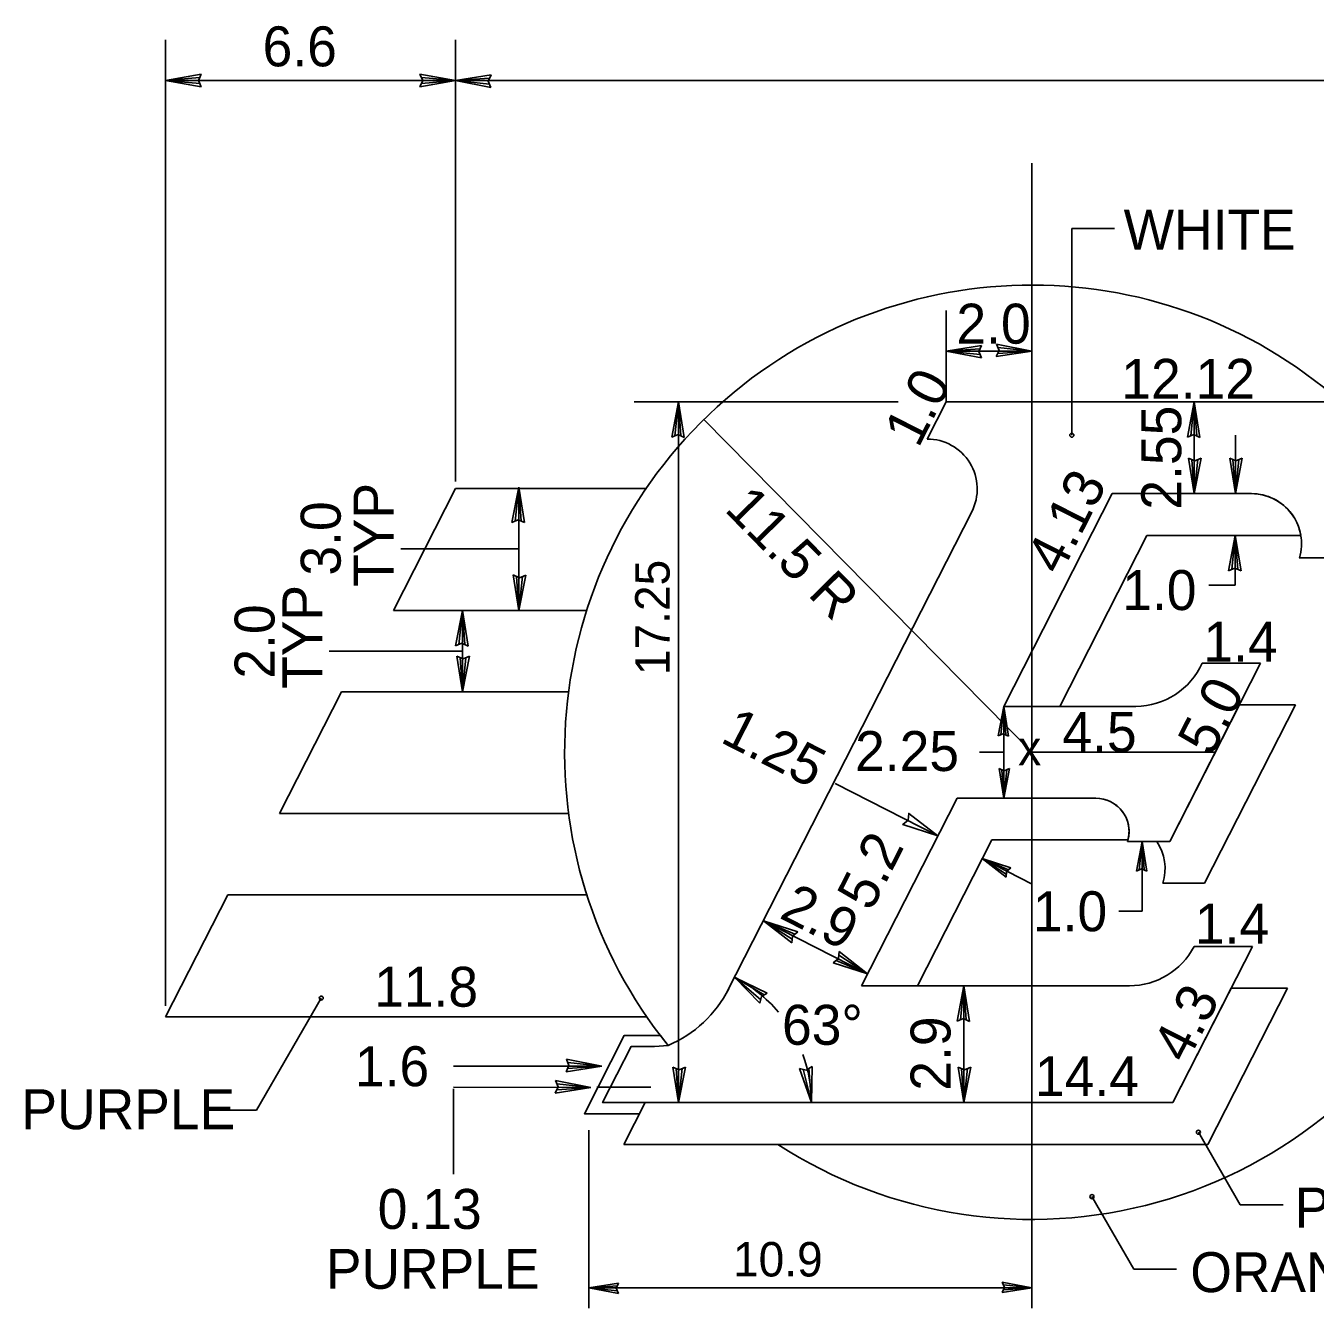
# Model space of a CAD drawing. Extents: x 10268197 to 10269179, y 2141503 to 2142677.
# Drawn here: x 10268594.16 to 10268616.76, y 2141973.76 to 2141996.23 of the extents above; entities that cross this region are included whole.
import ezdxf

# ---------------------------------------------------------------- set-up
doc = ezdxf.new("R2010")
doc.units = 0
for name, color, linetype in [('1', 7, 'Continuous'), ('20', 7, 'Continuous'), ('21', 7, 'Continuous'), ('52', 7, 'Continuous'), ('NonPlottingEle_dp', 7, 'Continuous'), ('North Arrow', 7, 'Continuous')]:
    doc.layers.add(name, color=color, linetype=linetype)

msp = doc.modelspace()

# ---------------------------------------------------------------- linework, layer by layer
at = {"layer": '1'}
for p, q in [((10268611.789, 2141983.501), (10268611.789, 2141993.824)), ((10268610.286, 2141989.641), (10268609.955, 2141988.99)), ((10268618.911, 2141989.641), (10268610.286, 2141989.641)), ((10268611.789, 2141983.501), (10268606.044, 2141989.334)), ((10268601.689, 2141988.121), (10268600.601, 2141985.986)), ((10268601.689, 2141988.121), (10268605.031, 2141988.121)), ((10268613.197, 2141988.033), (10268611.298, 2141984.305)), ((10268613.197, 2141988.033), (10268611.298, 2141984.305)), ((10268613.197, 2141988.033), (10268615.637, 2141988.033)), ((10268615.637, 2141988.033), (10268613.197, 2141988.033)), ((10268606.459, 2141979.318), (10268610.738, 2141987.715)), ((10268613.808, 2141987.302), (10268612.281, 2141984.305)), ((10268612.281, 2141984.305), (10268613.808, 2141987.302)), ((10268613.808, 2141987.302), (10268616.502, 2141987.302)), ((10268613.808, 2141987.302), (10268616.502, 2141987.302)), ((10268602.8, 2141987.067), (10268600.729, 2141987.067)), ((10268616.478, 2141986.906), (10268617.518, 2141986.906)), ((10268600.601, 2141985.986), (10268603.988, 2141985.986)), ((10268601.811, 2141985.274), (10268599.474, 2141985.274)), ((10268614.208, 2141981.938), (10268615.8, 2141985.064)), ((10268614.775, 2141985.065), (10268615.8, 2141985.064)), ((10268599.694, 2141984.562), (10268598.604, 2141982.426)), ((10268599.694, 2141984.562), (10268603.671, 2141984.562)), ((10268611.298, 2141984.305), (10268613.61, 2141984.305)), ((10268611.298, 2141984.305), (10268612.281, 2141984.305)), ((10268615.428, 2141984.333), (10268614.208, 2141981.938)), ((10268614.819, 2141981.207), (10268616.413, 2141984.333)), ((10268614.819, 2141981.207), (10268616.413, 2141984.333)), ((10268615.428, 2141984.333), (10268616.413, 2141984.333)), ((10268616.413, 2141984.333), (10268615.428, 2141984.333)), ((10268611.298, 2141983.501), (10268610.873, 2141983.501)), ((10268611.789, 2141973.759), (10268611.789, 2141983.501)), ((10268615.004, 2141983.501), (10268611.789, 2141983.501)), ((10268610.479, 2141982.697), (10268608.803, 2141979.408)), ((10268610.479, 2141982.697), (10268608.803, 2141979.408)), ((10268610.479, 2141982.697), (10268612.909, 2141982.697)), ((10268612.909, 2141982.697), (10268610.479, 2141982.697)), ((10268598.604, 2141982.426), (10268603.673, 2141982.427)), ((10268611.09, 2141981.966), (10268609.787, 2141979.407)), ((10268609.787, 2141979.407), (10268611.09, 2141981.966)), ((10268611.09, 2141981.966), (10268613.476, 2141981.966)), ((10268611.09, 2141981.966), (10268613.476, 2141981.966)), ((10268613.467, 2141981.938), (10268614.208, 2141981.938)), ((10268614.208, 2141981.938), (10268613.981, 2141981.938)), ((10268614.819, 2141981.207), (10268614.088, 2141981.207)), ((10268614.088, 2141981.207), (10268614.819, 2141981.207)), ((10268597.698, 2141981.003), (10268596.609, 2141978.867)), ((10268597.698, 2141981.003), (10268603.993, 2141981.003)), ((10268615.657, 2141980.096), (10268614.263, 2141977.361)), ((10268614.633, 2141980.096), (10268615.657, 2141980.096)), ((10268608.803, 2141979.408), (10268613.499, 2141979.408)), ((10268608.803, 2141979.408), (10268609.787, 2141979.407)), ((10268615.285, 2141979.365), (10268614.263, 2141977.361)), ((10268616.269, 2141979.365), (10268614.875, 2141976.63)), ((10268614.875, 2141976.63), (10268616.269, 2141979.365)), ((10268615.285, 2141979.365), (10268616.269, 2141979.365)), ((10268616.269, 2141979.365), (10268615.285, 2141979.365)), ((10268596.609, 2141978.867), (10268605.04, 2141978.867)), ((10268614.263, 2141977.361), (10268604.267, 2141977.361)), ((10268604.641, 2141976.63), (10268605.013, 2141977.361)), ((10268605.013, 2141977.361), (10268604.641, 2141976.63)), ((10268614.263, 2141977.361), (10268605.013, 2141977.361)), ((10268604.914, 2141977.166), (10268603.949, 2141977.166)), ((10268604.029, 2141973.759), (10268604.029, 2141976.879)), ((10268614.875, 2141976.63), (10268604.641, 2141976.63)), ((10268604.641, 2141976.63), (10268614.875, 2141976.63))]:
    msp.add_line(p, q, dxfattribs=at)
for centre, radius, start, end in [((10268611.789, 2141983.501), 8.187, 48.5904, 218.8792), ((10268609.956, 2141988.113), 0.877, 333.0033, 90.1042), ((10268615.638, 2141987.156), 0.877, 343.4611, 90), ((10268615.638, 2141987.156), 0.877, 9.5941, 90), ((10268613.611, 2141985.577), 1.272, 270, 336.2493), ((10268612.909, 2141982.112), 0.585, 342.6625, 90), ((10268612.909, 2141982.112), 0.585, 345.5225, 90), ((10268613.248, 2141981.457), 0.877, 343.4611, 33.2756), ((10268613.248, 2141981.457), 0.877, 343.4611, 33.2756), ((10268613.498, 2141980.687), 1.279, 270, 332.5096), ((10268611.789, 2141983.501), 8.187, 237.0648, 334.1734), ((10268604.576, 2141980.326), 2.136, 293.1567, 333.0112)]:
    msp.add_arc(centre, radius, start, end, dxfattribs=at)
at = {"layer": '20'}
for p, q in [((10268596.609, 2141979.056), (10268596.609, 2141995.984)), ((10268601.689, 2141989.283), (10268601.689, 2141995.984)), ((10268601.689, 2141995.272), (10268596.609, 2141995.272)), ((10268648.726, 2141995.272), (10268601.689, 2141995.272)), ((10268612.491, 2141992.679), (10268613.241, 2141992.68)), ((10268612.491, 2141989.057), (10268612.491, 2141992.679)), ((10268610.286, 2141989.641), (10268610.286, 2141991.243)), ((10268611.789, 2141990.532), (10268610.286, 2141990.532)), ((10268609.449, 2141989.641), (10268604.818, 2141989.641)), ((10268605.599, 2141977.361), (10268605.598, 2141989.641)), ((10268614.637, 2141989.641), (10268614.637, 2141988.033)), ((10268601.689, 2141988.246), (10268601.689, 2141989.283)), ((10268615.357, 2141989.059), (10268615.357, 2141988.033)), ((10268602.799, 2141988.149), (10268602.8, 2141985.986)), ((10268615.356, 2141987.302), (10268615.356, 2141986.426)), ((10268614.893, 2141986.426), (10268615.356, 2141986.426)), ((10268601.811, 2141985.986), (10268601.811, 2141984.562)), ((10268611.298, 2141984.305), (10268611.298, 2141982.697)), ((10268610.141, 2141982.034), (10268608.341, 2141982.952)), ((10268613.722, 2141981.938), (10268613.722, 2141980.714)), ((10268610.922, 2141981.637), (10268611.797, 2141981.191)), ((10268613.722, 2141980.714), (10268613.314, 2141980.715)), ((10268607.086, 2141980.549), (10268608.911, 2141979.619)), ((10268610.6, 2141979.407), (10268610.6, 2141977.361)), ((10268599.336, 2141979.193), (10268598.203, 2141977.231)), ((10268604.252, 2141978.002), (10268601.655, 2141978.002)), ((10268604.063, 2141977.629), (10268601.655, 2141977.63)), ((10268601.655, 2141976.11), (10268601.655, 2141977.606)), ((10268605.114, 2141977.63), (10268604.166, 2141977.63)), ((10268598.203, 2141977.231), (10268597.454, 2141977.231)), ((10268614.71, 2141976.843), (10268615.444, 2141975.571)), ((10268612.843, 2141975.714), (10268613.577, 2141974.443)), ((10268615.444, 2141975.571), (10268616.194, 2141975.571)), ((10268613.577, 2141974.443), (10268614.327, 2141974.442)), ((10268611.789, 2141974.117), (10268604.029, 2141974.117))]:
    msp.add_line(p, q, dxfattribs=at)
for centre in [(10268612.491, 2141989.057), (10268599.336, 2141979.193), (10268614.71, 2141976.843), (10268612.843, 2141975.714)]:
    msp.add_circle(centre, 0.0356, dxfattribs=at)
for start, end in [(40.0298, 62.999), (0, 19.9667)]:
    msp.add_arc((10268605.462, 2141977.361), 2.465, start, end, dxfattribs=at)
at = {"layer": '21'}
for p, q in [((10268596.609, 2141995.272), (10268597.231, 2141995.382)), ((10268597.183, 2141995.272), (10268597.231, 2141995.382)), ((10268601.689, 2141995.272), (10268601.067, 2141995.382)), ((10268601.067, 2141995.382), (10268601.115, 2141995.272)), ((10268601.689, 2141995.272), (10268602.313, 2141995.371)), ((10268602.263, 2141995.262), (10268602.313, 2141995.371)), ((10268596.609, 2141995.272), (10268597.205, 2141995.324)), ((10268596.609, 2141995.272), (10268597.23, 2141995.162)), ((10268596.609, 2141995.272), (10268597.206, 2141995.22)), ((10268597.23, 2141995.162), (10268597.183, 2141995.272)), ((10268601.689, 2141995.272), (10268601.067, 2141995.162)), ((10268601.115, 2141995.272), (10268601.067, 2141995.162)), ((10268601.689, 2141995.272), (10268601.092, 2141995.324)), ((10268601.689, 2141995.272), (10268601.092, 2141995.22)), ((10268601.689, 2141995.272), (10268602.286, 2141995.314)), ((10268601.689, 2141995.272), (10268602.309, 2141995.152)), ((10268601.689, 2141995.272), (10268602.285, 2141995.21)), ((10268602.309, 2141995.152), (10268602.263, 2141995.262)), ((10268610.286, 2141990.532), (10268610.91, 2141990.63)), ((10268610.86, 2141990.522), (10268610.91, 2141990.63)), ((10268611.789, 2141990.532), (10268611.169, 2141990.652)), ((10268611.169, 2141990.652), (10268611.215, 2141990.541)), ((10268610.286, 2141990.532), (10268610.884, 2141990.573)), ((10268610.286, 2141990.532), (10268610.906, 2141990.411)), ((10268610.286, 2141990.532), (10268610.882, 2141990.469)), ((10268610.906, 2141990.411), (10268610.86, 2141990.522)), ((10268611.215, 2141990.541), (10268611.165, 2141990.433)), ((10268611.789, 2141990.532), (10268611.165, 2141990.433)), ((10268611.789, 2141990.532), (10268611.192, 2141990.49)), ((10268611.789, 2141990.532), (10268611.193, 2141990.594)), ((10268605.598, 2141989.641), (10268605.478, 2141989.021)), ((10268605.598, 2141989.641), (10268605.536, 2141989.045)), ((10268605.598, 2141989.641), (10268605.698, 2141989.017)), ((10268605.598, 2141989.641), (10268605.64, 2141989.044)), ((10268614.637, 2141989.641), (10268614.517, 2141989.021)), ((10268614.637, 2141989.641), (10268614.575, 2141989.045)), ((10268614.637, 2141989.641), (10268614.736, 2141989.017)), ((10268614.637, 2141989.641), (10268614.679, 2141989.044)), ((10268605.478, 2141989.021), (10268605.589, 2141989.067)), ((10268605.589, 2141989.067), (10268605.698, 2141989.017)), ((10268614.517, 2141989.021), (10268614.628, 2141989.067)), ((10268614.628, 2141989.067), (10268614.736, 2141989.017)), ((10268614.637, 2141988.033), (10268614.538, 2141988.657)), ((10268614.647, 2141988.608), (10268614.538, 2141988.657)), ((10268614.637, 2141988.033), (10268614.596, 2141988.63)), ((10268614.637, 2141988.033), (10268614.758, 2141988.653)), ((10268614.637, 2141988.033), (10268614.7, 2141988.629)), ((10268614.758, 2141988.653), (10268614.647, 2141988.608)), ((10268615.357, 2141988.033), (10268615.258, 2141988.657)), ((10268615.366, 2141988.607), (10268615.258, 2141988.657)), ((10268615.357, 2141988.033), (10268615.315, 2141988.63)), ((10268615.357, 2141988.033), (10268615.477, 2141988.653)), ((10268615.357, 2141988.033), (10268615.419, 2141988.629)), ((10268615.477, 2141988.653), (10268615.366, 2141988.607)), ((10268602.799, 2141988.149), (10268602.679, 2141987.529)), ((10268602.799, 2141988.149), (10268602.737, 2141987.553)), ((10268602.799, 2141988.149), (10268602.898, 2141987.525)), ((10268602.799, 2141988.149), (10268602.841, 2141987.551)), ((10268602.679, 2141987.529), (10268602.79, 2141987.574)), ((10268602.79, 2141987.574), (10268602.898, 2141987.525)), ((10268615.356, 2141987.302), (10268615.236, 2141986.682)), ((10268615.356, 2141987.302), (10268615.294, 2141986.706)), ((10268615.356, 2141987.302), (10268615.456, 2141986.678)), ((10268615.356, 2141987.302), (10268615.398, 2141986.705)), ((10268602.8, 2141985.986), (10268602.701, 2141986.61)), ((10268602.81, 2141986.56), (10268602.701, 2141986.61)), ((10268602.8, 2141985.986), (10268602.758, 2141986.583)), ((10268602.8, 2141985.986), (10268602.92, 2141986.606)), ((10268602.8, 2141985.986), (10268602.862, 2141986.582)), ((10268602.92, 2141986.606), (10268602.81, 2141986.56)), ((10268615.236, 2141986.682), (10268615.347, 2141986.728)), ((10268615.347, 2141986.728), (10268615.456, 2141986.678)), ((10268601.811, 2141985.986), (10268601.691, 2141985.366)), ((10268601.811, 2141985.986), (10268601.749, 2141985.39)), ((10268601.811, 2141985.986), (10268601.91, 2141985.362)), ((10268601.811, 2141985.986), (10268601.853, 2141985.389)), ((10268601.691, 2141985.366), (10268601.801, 2141985.412)), ((10268601.801, 2141985.412), (10268601.91, 2141985.362)), ((10268601.811, 2141984.562), (10268601.712, 2141985.186)), ((10268601.821, 2141985.136), (10268601.712, 2141985.186)), ((10268601.811, 2141984.562), (10268601.932, 2141985.182)), ((10268601.932, 2141985.182), (10268601.821, 2141985.136)), ((10268601.811, 2141984.562), (10268601.769, 2141985.159)), ((10268601.811, 2141984.562), (10268601.873, 2141985.158)), ((10268611.298, 2141984.305), (10268611.198, 2141983.788)), ((10268611.298, 2141984.305), (10268611.246, 2141983.808)), ((10268611.298, 2141984.305), (10268611.381, 2141983.784)), ((10268611.298, 2141984.305), (10268611.333, 2141983.807)), ((10268611.198, 2141983.788), (10268611.29, 2141983.826)), ((10268611.29, 2141983.826), (10268611.381, 2141983.784)), ((10268611.298, 2141982.697), (10268611.216, 2141983.217)), ((10268611.306, 2141983.176), (10268611.216, 2141983.217)), ((10268611.298, 2141982.697), (10268611.263, 2141983.195)), ((10268611.298, 2141982.697), (10268611.399, 2141983.214)), ((10268611.298, 2141982.697), (10268611.35, 2141983.194)), ((10268611.399, 2141983.214), (10268611.306, 2141983.176)), ((10268613.722, 2141981.938), (10268613.622, 2141981.42)), ((10268613.722, 2141981.938), (10268613.67, 2141981.44)), ((10268613.722, 2141981.938), (10268613.804, 2141981.417)), ((10268613.722, 2141981.938), (10268613.756, 2141981.44)), ((10268610.922, 2141981.637), (10268611.424, 2141981.475)), ((10268610.922, 2141981.637), (10268611.338, 2141981.313)), ((10268610.922, 2141981.637), (10268611.342, 2141981.365)), ((10268610.922, 2141981.637), (10268611.382, 2141981.442)), ((10268611.338, 2141981.313), (10268611.346, 2141981.412)), ((10268611.346, 2141981.412), (10268611.424, 2141981.475)), ((10268613.622, 2141981.42), (10268613.714, 2141981.459)), ((10268613.714, 2141981.459), (10268613.804, 2141981.417)), ((10268607.086, 2141980.549), (10268607.687, 2141980.354)), ((10268607.086, 2141980.549), (10268607.584, 2141980.16)), ((10268607.086, 2141980.549), (10268607.589, 2141980.223)), ((10268607.086, 2141980.549), (10268607.637, 2141980.315)), ((10268607.584, 2141980.16), (10268607.593, 2141980.279)), ((10268607.593, 2141980.279), (10268607.687, 2141980.354)), ((10268608.413, 2141980.008), (10268608.404, 2141979.889)), ((10268608.911, 2141979.619), (10268608.413, 2141980.008)), ((10268608.404, 2141979.889), (10268608.31, 2141979.814)), ((10268608.911, 2141979.619), (10268608.31, 2141979.814)), ((10268608.911, 2141979.619), (10268608.359, 2141979.853)), ((10268608.911, 2141979.619), (10268608.408, 2141979.945)), ((10268606.585, 2141979.557), (10268607.153, 2141979.282)), ((10268606.585, 2141979.557), (10268607.025, 2141979.104)), ((10268606.585, 2141979.557), (10268607.038, 2141979.165)), ((10268606.585, 2141979.557), (10268607.099, 2141979.25)), ((10268610.6, 2141979.407), (10268610.48, 2141978.787)), ((10268610.6, 2141979.407), (10268610.538, 2141978.811)), ((10268610.6, 2141979.407), (10268610.699, 2141978.784)), ((10268610.6, 2141979.407), (10268610.642, 2141978.81)), ((10268607.025, 2141979.104), (10268607.051, 2141979.221)), ((10268607.051, 2141979.221), (10268607.153, 2141979.282)), ((10268610.48, 2141978.787), (10268610.591, 2141978.833)), ((10268610.591, 2141978.833), (10268610.699, 2141978.784)), ((10268603.678, 2141978.012), (10268603.628, 2141977.903)), ((10268604.252, 2141978.002), (10268603.628, 2141977.903)), ((10268604.252, 2141978.002), (10268603.632, 2141978.122)), ((10268603.632, 2141978.122), (10268603.678, 2141978.012)), ((10268604.252, 2141978.002), (10268603.655, 2141977.96)), ((10268604.252, 2141978.002), (10268603.656, 2141978.064)), ((10268605.599, 2141977.361), (10268605.5, 2141977.985)), ((10268605.609, 2141977.935), (10268605.5, 2141977.985)), ((10268605.599, 2141977.361), (10268605.557, 2141977.958)), ((10268605.599, 2141977.361), (10268605.719, 2141977.981)), ((10268605.599, 2141977.361), (10268605.661, 2141977.957)), ((10268605.719, 2141977.981), (10268605.609, 2141977.935)), ((10268607.927, 2141977.365), (10268607.721, 2141977.962)), ((10268607.837, 2141977.932), (10268607.721, 2141977.962)), ((10268607.938, 2141977.996), (10268607.837, 2141977.932)), ((10268607.927, 2141977.365), (10268607.884, 2141977.963)), ((10268607.927, 2141977.365), (10268607.938, 2141977.996)), ((10268610.6, 2141977.361), (10268610.502, 2141977.985)), ((10268610.61, 2141977.935), (10268610.502, 2141977.985)), ((10268610.6, 2141977.361), (10268610.559, 2141977.958)), ((10268610.6, 2141977.361), (10268610.721, 2141977.981)), ((10268610.6, 2141977.361), (10268610.663, 2141977.957)), ((10268610.721, 2141977.981), (10268610.61, 2141977.935)), ((10268604.063, 2141977.629), (10268603.442, 2141977.75)), ((10268603.442, 2141977.75), (10268603.488, 2141977.639)), ((10268607.927, 2141977.365), (10268607.782, 2141977.946)), ((10268603.488, 2141977.639), (10268603.439, 2141977.53)), ((10268604.063, 2141977.629), (10268603.439, 2141977.53)), ((10268604.063, 2141977.629), (10268603.465, 2141977.588)), ((10268604.063, 2141977.629), (10268603.466, 2141977.692)), ((10268604.029, 2141974.117), (10268604.549, 2141974.199)), ((10268604.029, 2141974.117), (10268604.527, 2141974.152)), ((10268604.029, 2141974.117), (10268604.546, 2141974.016)), ((10268604.029, 2141974.117), (10268604.527, 2141974.065)), ((10268604.508, 2141974.109), (10268604.549, 2141974.199)), ((10268604.546, 2141974.016), (10268604.508, 2141974.109)), ((10268611.31, 2141974.125), (10268611.269, 2141974.034)), ((10268611.789, 2141974.117), (10268611.269, 2141974.034)), ((10268611.789, 2141974.117), (10268611.272, 2141974.217)), ((10268611.272, 2141974.217), (10268611.31, 2141974.125)), ((10268611.789, 2141974.117), (10268611.291, 2141974.082)), ((10268611.789, 2141974.117), (10268611.292, 2141974.169))]:
    msp.add_line(p, q, dxfattribs=at)
at = {"layer": '52'}
msp.add_lwpolyline([(10268610.141, 2141982.034), (10268609.529, 2141982.234), (10268609.621, 2141982.309), (10268609.634, 2141982.43)], close=True, dxfattribs=at)
at = {"layer": 'NonPlottingEle_dp'}
for p, q in [((10268604.767, 2141978.344), (10268605.177, 2141978.344)), ((10268605.177, 2141978.344), (10268605.416, 2141978.362))]:
    msp.add_line(p, q, dxfattribs=at)
msp.add_lwpolyline([(10268605.284, 2141978.539), (10268604.647, 2141978.539), (10268603.949, 2141977.166), (10268604.914, 2141977.166), (10268605.013, 2141977.361), (10268604.267, 2141977.361), (10268604.767, 2141978.344), (10268605.177, 2141978.344), (10268605.416, 2141978.362)], close=True, dxfattribs=at)
at = {"layer": 'North Arrow'}
for p, q in [((10268604.647, 2141978.539), (10268603.949, 2141977.166)), ((10268604.647, 2141978.539), (10268605.284, 2141978.539)), ((10268604.767, 2141978.344), (10268604.267, 2141977.361))]:
    msp.add_line(p, q, dxfattribs=at)

# ---------------------------------------------------------------- texts
at = {"layer": '1'}
msp.add_text('x', height=0.604, dxfattribs=at).set_placement((10268611.551, 2141983.274))
at = {"layer": '20'}
for s, height, p in [('6.6', 0.7, (10268598.309, 2141995.52)), ('WHITE', 0.7, (10268613.399, 2141992.309)), ('2.0', 0.7, (10268610.469, 2141990.661)), ('12.12', 0.7, (10268613.359, 2141989.694)), ('1.0', 0.7, (10268613.375, 2141985.993)), ('1.4', 0.7, (10268614.797, 2141985.088)), ('4.5', 0.7, (10268612.326, 2141983.507)), ('1.0', 0.7, (10268611.809, 2141980.365)), ('1.4', 0.7, (10268614.647, 2141980.149)), ('11.8', 0.7, (10268600.263, 2141979.042)), ('63°', 0.7, (10268607.412, 2141978.375)), ('1.6', 0.7, (10268599.927, 2141977.649)), ('14.4', 0.7, (10268611.845, 2141977.475)), ('PURPLE', 0.7, (10268594.082, 2141976.895)), ('0.13', 0.7, (10268600.326, 2141975.149)), ('PURPLE', 0.7, (10268616.398, 2141975.173)), ('PURPLE', 0.7, (10268599.417, 2141974.099)), ('10.9', 0.6037, (10268606.553, 2141974.315)), ('ORANGE', 0.7, (10268614.568, 2141974.041))]:
    msp.add_text(s, height=height, dxfattribs=at).set_placement(p)
for s, height, rotation, p in [('1.0', 0.7, 62.9854, (10268609.8, 2141988.817)), ('2.55', 0.7, 90, (10268614.409, 2141987.752)), ('4.13', 0.7, 63.012, (10268612.289, 2141986.583)), ('TYP', 0.7, 90, (10268600.603, 2141986.4)), ('11.5 R', 0.7, 314.5624, (10268606.386, 2141987.741)), ('3.0', 0.7, 90, (10268599.677, 2141986.597)), ('17.25', 0.6037, 90, (10268605.442, 2141984.853)), ('TYP', 0.7, 90, (10268599.356, 2141984.612)), ('2.0', 0.7, 90, (10268598.518, 2141984.791)), ('5.0', 0.7, 63.0087, (10268614.941, 2141983.408)), ('1.25', 0.7, 333.0041, (10268606.31, 2141983.688)), ('2.25', 0.7, 360, (10268608.693, 2141983.172)), ('5.2', 0.7, 63.0001, (10268608.973, 2141980.694)), ('2.9', 0.7, 333.0028, (10268607.345, 2141980.608)), ('4.3', 0.7, 62.9952, (10268614.502, 2141978.026)), ('2.9', 0.7, 90, (10268610.365, 2141977.57))]:
    msp.add_text(s, height=height, rotation=rotation, dxfattribs=at).set_placement(p)

doc.saveas('drawing.dxf')
